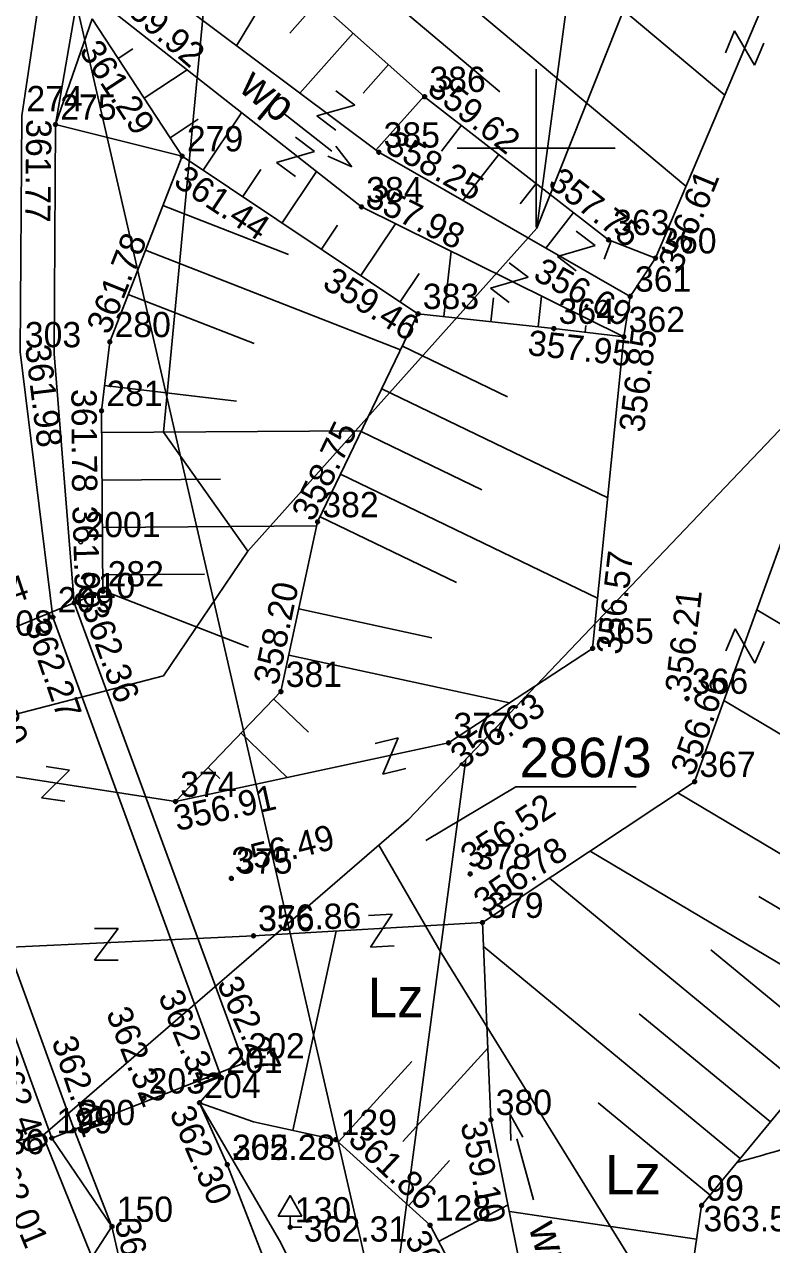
# Model space of a CAD drawing. Extents: x 4635329 to 4651863, y 5356628 to 5367582.
# Drawn here: x 4651733.8 to 4651757.46, y 5357115.3 to 5357153.92 of the extents above; entities that cross this region are included whole.
import ezdxf

# ---------------------------------------------------------------- set-up
doc = ezdxf.new("R2010")
doc.units = 0
for name, color, linetype in [('Level 12', 7, 'Continuous'), ('Level 2', 7, 'Continuous'), ('Level 20', 7, 'Continuous'), ('Level 24', 7, 'Continuous'), ('Level 29', 7, 'Continuous'), ('Level 4', 7, 'Continuous'), ('Level 44', 7, 'Continuous'), ('Level 45', 7, 'Continuous'), ('Level 46', 7, 'Continuous'), ('Level 48', 7, 'Continuous'), ('Level 5', 7, 'Continuous'), ('Level 50', 7, 'Continuous'), ('Level 51', 7, 'Continuous'), ('Level 53', 7, 'Continuous'), ('Level 60', 7, 'Continuous'), ('Level 63', 7, 'Continuous')]:
    doc.layers.add(name, color=color, linetype=linetype)

msp = doc.modelspace()

# ---------------------------------------------------------------- linework, layer by layer
at = {"layer": 'Level 2'}
msp.add_line((4651752.271, 5357081.395), (4651734.633, 5357158.117), dxfattribs=at)
at = {"layer": 'Level 20'}
for p, q in [((4651734.7, 5357135.16), (4651740.04, 5357120.58)), ((4651739.34, 5357119.79), (4651740.22, 5357117.83)), ((4651740.22, 5357117.83), (4651742.64, 5357111.63))]:
    msp.add_line(p, q, dxfattribs=at)
for points in [[(4651756.54, 5357214.25), (4651747.08, 5357190.33), (4651742.11, 5357177.45), (4651737.72, 5357166.81), (4651734.98, 5357158.12), (4651734.207, 5357154.352), (4651733.71, 5357151.02), (4651733.66, 5357143.55), (4651734.7, 5357135.16)], [(4651730.09, 5357133.42), (4651735.37, 5357118.93)], [(4651729.32, 5357025.03), (4651737.42, 5357039.16), (4651742.88, 5357049.73), (4651744.63, 5357054), (4651745.586, 5357056.87), (4651746.84, 5357061.68), (4651747.431, 5357065.159), (4651747.81, 5357068.95), (4651747.54, 5357079.35), (4651746.07, 5357086.39), (4651738.98, 5357107.74), (4651737.87, 5357110.18), (4651736.57, 5357115.87), (4651735.37, 5357118.93)], [(4651736.57, 5357115.87), (4651734.62, 5357112.86), (4651733.779, 5357107.317), (4651731.11, 5357098.85), (4651730.6, 5357091.37), (4651722.32, 5357083.58)]]:
    msp.add_lwpolyline(points, dxfattribs=at)
at = {"layer": 'Level 24'}
for p, q in [((4651742.21, 5357115.85), (4651742.21, 5357116.2)), ((4651742.585, 5357115.85), (4651742.21, 5357115.85))]:
    msp.add_line(p, q, dxfattribs=at)
msp.add_lwpolyline([(4651742.585, 5357116.2), (4651741.835, 5357116.2), (4651742.21, 5357116.85)], close=True, dxfattribs=at)
at = {"layer": 'Level 29'}
msp.add_lwpolyline([(4651734.66, 5357118.67), (4651740.74, 5357121.04), (4651735.37, 5357135.61), (4651729.39, 5357133.15)], close=True, dxfattribs=at)
at = {"layer": 'Level 4'}
for p, q in [((4651763.487, 5357181.344), (4651750.024, 5357147.467)), ((4651751.63, 5357159.48), (4651750.024, 5357147.467)), ((4651738.202, 5357141.009), (4651739.93, 5357159.265)), ((4651750.024, 5357147.467), (4651740.87, 5357137.248)), ((4651745.963, 5357128.756), (4651762.032, 5357145.618)), ((4651740.87, 5357137.248), (4651738.202, 5357141.009)), ((4651738.202, 5357133.305), (4651740.87, 5357137.248)), ((4651729.077, 5357130.935), (4651738.202, 5357133.305)), ((4651747.779, 5357130.661), (4651745.31, 5357112.19)), ((4651749.355, 5357129.788), (4651746.507, 5357128.092)), ((4651753.172, 5357129.788), (4651749.355, 5357129.788)), ((4651734.382, 5357118.748), (4651745.963, 5357128.756)), ((4651746.966, 5357124.583), (4651745.017, 5357127.939)), ((4651746.966, 5357124.583), (4651754.512, 5357112.38)), ((4651726.932, 5357117.207), (4651734.382, 5357118.748)), ((4651738.719, 5357108.044), (4651734.382, 5357118.748))]:
    msp.add_line(p, q, dxfattribs=at)
at = {"layer": 'Level 44'}
for centre in [(4651746.47, 5357151.63), (4651734.78, 5357150.75), (4651738.79, 5357149.75), (4651745.02, 5357149.87), (4651744.47, 5357148.14), (4651752.29, 5357147.1), (4651753.78, 5357146.52), (4651752.98, 5357145.31), (4651746.26, 5357144.76), (4651750.56, 5357144.29), (4651736.5, 5357143.87), (4651752.78, 5357144.03), (4651736.24, 5357141.69), (4651743.08, 5357138.17), (4651736.28, 5357135.98), (4651735.37, 5357135.61), (4651734.7, 5357135.16), (4651751.79, 5357134.17), (4651741.92, 5357132.8), (4651754.78, 5357132.58), (4651747.23, 5357131.18), (4651755.02, 5357129.95), (4651738.58, 5357129.32), (4651740.35, 5357126.89), (4651747.91, 5357127.03), (4651748.3, 5357125.49), (4651741.05, 5357125.07), (4651740.74, 5357121.04), (4651740.04, 5357120.58), (4651737.58, 5357119.93), (4651739.34, 5357119.79), (4651748.57, 5357119.25), (4651735.37, 5357118.93), (4651734.66, 5357118.67), (4651743.66, 5357118.62), (4651740.22, 5357117.83), (4651755.24, 5357116.54), (4651736.57, 5357115.87), (4651742.21, 5357115.85), (4651746.64, 5357115.91)]:
    msp.add_circle(centre, 0.04, dxfattribs=at)
at = {"layer": 'Level 46'}
for points in [[(4651790.492, 5357125.623), (4651787.46, 5357124.319), (4651783.61, 5357123.258), (4651779.365, 5357124.047), (4651775.849, 5357125.502), (4651773.423, 5357125.502), (4651767.19, 5357123.23), (4651762.733, 5357120.713), (4651758.853, 5357118.681), (4651756.364, 5357117.902)], [(4651754.793, 5357102.394), (4651755.147, 5357104.754), (4651755.905, 5357108.242), (4651755.935, 5357111.456), (4651757.114, 5357114.234), (4651759.084, 5357116.205), (4651762.904, 5357118.146), (4651766.694, 5357118.419), (4651770.685, 5357117.772)]]:
    msp.add_spline(points, degree=3, dxfattribs=at)
at = {"layer": 'Level 48'}
for p, q in [((4651746.469, 5357159.664), (4651755.973, 5357151.681)), ((4651744.54, 5357157.367), (4651754.746, 5357148.794)), ((4651743.575, 5357156.219), (4651748.854, 5357151.784)), ((4651741.877, 5357155.511), (4651740.515, 5357153.245)), ((4651743.091, 5357154.641), (4651742.202, 5357153.644)), ((4651734.78, 5357150.75), (4651735.94, 5357154.09)), ((4651735.94, 5357154.09), (4651738.79, 5357149.75)), ((4651744.211, 5357153.643), (4651742.518, 5357151.744)), ((4651736.763, 5357152.836), (4651737.234, 5357153.145)), ((4651737.587, 5357151.582), (4651738.949, 5357152.477)), ((4651745.331, 5357152.645), (4651744.527, 5357151.743)), ((4651746.451, 5357151.647), (4651744.928, 5357149.939)), ((4651738.41, 5357150.329), (4651739.302, 5357150.914)), ((4651739.462, 5357149.301), (4651740.676, 5357151.12)), ((4651747.633, 5357150.725), (4651747, 5357149.911)), ((4651748.817, 5357149.803), (4651747.682, 5357148.345)), ((4651740.709, 5357148.468), (4651741.284, 5357149.329)), ((4651741.956, 5357147.635), (4651743.043, 5357149.261)), ((4651750.001, 5357148.882), (4651749.499, 5357148.237)), ((4651738.18, 5357148.184), (4651742.16, 5357146.634)), ((4651751.184, 5357147.961), (4651750.311, 5357146.839)), ((4651743.204, 5357146.802), (4651743.715, 5357147.567)), ((4651744.451, 5357145.968), (4651745.546, 5357147.608)), ((4651752.382, 5357147.064), (4651752.158, 5357146.487)), ((4651737.629, 5357146.77), (4651745.711, 5357143.622)), ((4651747.08, 5357144.67), (4651747.306, 5357146.738)), ((4651745.698, 5357145.135), (4651746.3, 5357146.036)), ((4651737.085, 5357145.372), (4651741.071, 5357143.82)), ((4651748.571, 5357144.507), (4651748.654, 5357145.268)), ((4651750.062, 5357144.344), (4651750.169, 5357145.322)), ((4651743.08, 5357138.17), (4651746.26, 5357144.76)), ((4651751.552, 5357144.174), (4651751.578, 5357144.393)), ((4651745.767, 5357143.738), (4651749.097, 5357142.131)), ((4651736.336, 5357142.492), (4651740.51, 5357141.994)), ((4651745.115, 5357142.387), (4651752.268, 5357138.935)), ((4651736.245, 5357140.998), (4651744.472, 5357141.055)), ((4651744.463, 5357141.036), (4651748.286, 5357139.192)), ((4651743.811, 5357139.685), (4651751.949, 5357135.758)), ((4651736.255, 5357139.498), (4651740.001, 5357139.524)), ((4651741.92, 5357132.8), (4651743.08, 5357138.17)), ((4651743.159, 5357138.335), (4651747.475, 5357136.252)), ((4651736.266, 5357137.998), (4651743.053, 5357138.045)), ((4651736.276, 5357136.498), (4651739.502, 5357136.52)), ((4651736.28, 5357136.006), (4651740.891, 5357134.21)), ((4651742.485, 5357135.416), (4651746.699, 5357134.506)), ((4651764.981, 5357130.639), (4651756.987, 5357135.393)), ((4651742.168, 5357133.95), (4651749.153, 5357132.441)), ((4651738.58, 5357129.32), (4651741.92, 5357132.8)), ((4651741.696, 5357132.567), (4651742.793, 5357131.514)), ((4651763.448, 5357128.06), (4651755.949, 5357132.52)), ((4651740.657, 5357131.484), (4651742.119, 5357130.081)), ((4651739.619, 5357130.402), (4651739.984, 5357130.051)), ((4651761.78, 5357125.255), (4651754.483, 5357129.594)), ((4651760.247, 5357122.676), (4651751.71, 5357127.753)), ((4651758.373, 5357120.337), (4651750.422, 5357126.898)), ((4651761.013, 5357123.966), (4651757.055, 5357126.32)), ((4651742.3, 5357118.915), (4651743.667, 5357125.222)), ((4651756.464, 5357118.023), (4651748.333, 5357124.732)), ((4651759.328, 5357121.494), (4651755.528, 5357124.63)), ((4651757.419, 5357119.18), (4651753.267, 5357122.606)), ((4651745.78, 5357118.561), (4651748.472, 5357121.521)), ((4651743.74, 5357118.547), (4651746.06, 5357121.098)), ((4651755.509, 5357116.866), (4651751.965, 5357119.791)), ((4651745.959, 5357116.529), (4651747.261, 5357117.961)), ((4651746.91, 5357115.397), (4651749.112, 5357116.557)), ((4651755.083, 5357115.475), (4651749.154, 5357116.349))]:
    msp.add_line(p, q, dxfattribs=at)
for points in [[(4651788.23, 5357177.15), (4651778.95, 5357165), (4651774.56, 5357160.24), (4651772.52, 5357151.19), (4651770.34, 5357137.07), (4651766.1, 5357132.52), (4651760.1, 5357122.43), (4651755.24, 5357116.54), (4651754.43, 5357111.05), (4651754.06, 5357101.72), (4651764.92, 5357096.97)], [(4651736.04, 5357158.01), (4651734.78, 5357150.75)], [(4651753.78, 5357146.52), (4651752.29, 5357147.1), (4651746.47, 5357151.63), (4651742.61, 5357155.07), (4651738.55, 5357157.51)], [(4651734.78, 5357150.75), (4651734.734, 5357143.494), (4651735.37, 5357135.61)], [(4651735.37, 5357135.61), (4651736.28, 5357135.98), (4651736.24, 5357141.69), (4651736.5, 5357143.87), (4651738.79, 5357149.75), (4651734.78, 5357150.75)], [(4651738.79, 5357149.75), (4651746.26, 5357144.76), (4651750.56, 5357144.29), (4651752.78, 5357144.03)], [(4651739.34, 5357119.79), (4651740.04, 5357120.58)], [(4651739.34, 5357119.79), (4651741.05, 5357119.186), (4651743.66, 5357118.62)], [(4651739.34, 5357119.79), (4651741.917, 5357115.357), (4651743.483, 5357112.18), (4651749.82, 5357100.94)], [(4651734.66, 5357118.67), (4651736.57, 5357115.87)], [(4651749.82, 5357100.94), (4651748.78, 5357111.85), (4651746.64, 5357115.91), (4651743.66, 5357118.62)]]:
    msp.add_lwpolyline(points, dxfattribs=at)
at = {"layer": 'Level 50'}
for p, q in [((4651762.59, 5357167.25), (4651753.78, 5357146.52)), ((4651736.97, 5357155.9), (4651745.02, 5357149.87)), ((4651744.47, 5357148.14), (4651736.5, 5357154.4)), ((4651741.955, 5357151.138), (4651743.53, 5357149.905)), ((4651743.653, 5357150.062), (4651744.16, 5357149.412)), ((4651744.16, 5357149.412), (4651743.406, 5357149.748)), ((4651745.02, 5357149.87), (4651752.98, 5357145.31)), ((4651752.78, 5357144.03), (4651744.47, 5357148.14)), ((4651753.78, 5357146.52), (4651752.98, 5357145.31)), ((4651752.98, 5357145.31), (4651752.78, 5357144.03)), ((4651752.78, 5357144.03), (4651751.79, 5357134.17)), ((4651755.02, 5357129.95), (4651760.04, 5357143.84)), ((4651751.79, 5357134.17), (4651747.23, 5357131.18)), ((4651738.58, 5357129.32), (4651724.05, 5357131.57)), ((4651747.23, 5357131.18), (4651738.58, 5357129.32)), ((4651748.3, 5357125.49), (4651755.02, 5357129.95)), ((4651741.05, 5357125.07), (4651748.3, 5357125.49)), ((4651748.3, 5357125.49), (4651748.57, 5357119.25)), ((4651730.04, 5357124.56), (4651741.05, 5357125.07)), ((4651748.57, 5357119.25), (4651750.15, 5357111.4)), ((4651749.198, 5357118.595), (4651749.181, 5357119.419)), ((4651749.181, 5357119.419), (4651749.584, 5357118.699)), ((4651749.916, 5357116.717), (4651749.391, 5357118.647))]:
    msp.add_line(p, q, dxfattribs=at)
at = {"layer": 'Level 53'}
for p, q in [((4651756.286, 5357153.712), (4651755.993, 5357153.021)), ((4651756.914, 5357152.631), (4651756.286, 5357153.712)), ((4651757.207, 5357153.322), (4651756.914, 5357152.631)), ((4651743.659, 5357151.818), (4651744.257, 5357151.365)), ((4651744.257, 5357151.365), (4651743.056, 5357151.021)), ((4651743.056, 5357151.021), (4651743.654, 5357150.568)), ((4651742.383, 5357150.352), (4651742.983, 5357149.901)), ((4651742.983, 5357149.901), (4651741.783, 5357149.552)), ((4651741.783, 5357149.552), (4651742.383, 5357149.101)), ((4651751.273, 5357147.37), (4651751.873, 5357146.919)), ((4651751.873, 5357146.919), (4651750.673, 5357146.57)), ((4651750.673, 5357146.57), (4651751.273, 5357146.119)), ((4651749.152, 5357146.37), (4651749.752, 5357145.919)), ((4651749.752, 5357145.919), (4651748.552, 5357145.57)), ((4651748.552, 5357145.57), (4651749.152, 5357145.119)), ((4651756.302, 5357134.786), (4651756.005, 5357134.097)), ((4651756.923, 5357133.701), (4651756.302, 5357134.786)), ((4651757.22, 5357134.39), (4651756.923, 5357133.701)), ((4651745.637, 5357131.334), (4651744.908, 5357131.155)), ((4651745.147, 5357130.184), (4651745.637, 5357131.334)), ((4651735.226, 5357130.318), (4651734.485, 5357130.431)), ((4651745.875, 5357130.363), (4651745.147, 5357130.184)), ((4651734.334, 5357129.442), (4651735.226, 5357130.318)), ((4651735.076, 5357129.329), (4651734.334, 5357129.442)), ((4651745.446, 5357125.754), (4651744.697, 5357125.71)), ((4651744.756, 5357124.712), (4651745.446, 5357125.754)), ((4651736.768, 5357125.303), (4651736.018, 5357125.303)), ((4651736.018, 5357124.303), (4651736.768, 5357125.303)), ((4651745.504, 5357124.756), (4651744.756, 5357124.712)), ((4651736.768, 5357124.303), (4651736.018, 5357124.303))]:
    msp.add_line(p, q, dxfattribs=at)
at = {"layer": 'Level 60'}
for p, q in [((4651750, 5357147.5), (4651750, 5357152.5)), ((4651747.5, 5357150), (4651752.5, 5357150))]:
    msp.add_line(p, q, dxfattribs=at)
at = {"layer": 'Level 63'}
for centre in [(4651746.47, 5357151.63), (4651734.78, 5357150.75), (4651738.79, 5357149.75), (4651745.02, 5357149.87), (4651744.47, 5357148.14), (4651752.29, 5357147.1), (4651753.78, 5357146.52), (4651752.98, 5357145.31), (4651746.26, 5357144.76), (4651750.56, 5357144.29), (4651736.5, 5357143.87), (4651752.78, 5357144.03), (4651736.24, 5357141.69), (4651743.08, 5357138.17), (4651735.58, 5357137.54), (4651735.58, 5357137.54), (4651735.58, 5357137.54), (4651735.58, 5357137.54), (4651736.28, 5357135.98), (4651735.37, 5357135.61), (4651734.7, 5357135.16), (4651751.79, 5357134.17), (4651741.92, 5357132.8), (4651754.78, 5357132.58), (4651747.23, 5357131.18), (4651755.02, 5357129.95), (4651738.58, 5357129.32), (4651740.35, 5357126.89), (4651747.91, 5357127.03), (4651748.3, 5357125.49), (4651741.05, 5357125.07), (4651740.74, 5357121.04), (4651740.04, 5357120.58), (4651737.58, 5357119.93), (4651739.34, 5357119.79), (4651748.57, 5357119.25), (4651735.37, 5357118.93), (4651734.66, 5357118.67), (4651743.66, 5357118.62), (4651740.22, 5357117.83), (4651755.24, 5357116.54), (4651736.57, 5357115.87), (4651742.21, 5357115.85), (4651746.64, 5357115.91)]:
    msp.add_circle(centre, 0.06, dxfattribs=at)

# ---------------------------------------------------------------- texts
at = {"layer": 'Level 12'}
for p in [(4651744.671, 5357122.494), (4651752.184, 5357116.889)]:
    msp.add_text('Lz', height=1.25, dxfattribs=at).set_placement(p)
at = {"layer": 'Level 45'}
for s, rotation, p in [('359.92', 318.939, (4651736.594, 5357154.652)), ('361.29', 303.2464, (4651735.51, 5357153.08)), ('359.62', 321.8519, (4651746.51, 5357151.785)), ('361.77', 269.3178, (4651733.857, 5357150.923)), ('358.25', 330.7048, (4651745.177, 5357149.907)), ('361.44', 326.5821, (4651738.478, 5357148.847)), ('357.75', 322.1273, (4651750.335, 5357148.821)), ('356.61', 67.6009, (4651754.574, 5357146.063)), ('357.98', 333.8526, (4651744.54, 5357148.215)), ('361.78', 68.2406, (4651736.478, 5357144.065)), ('359.46', 327.8466, (4651743.19, 5357145.612)), ('356.69', 331.5925, (4651749.866, 5357145.87)), ('357.95', 353.6699, (4651749.706, 5357143.456)), ('356.85', 82.8332, (4651753.411, 5357140.978)), ('361.98', 276.9697, (4651733.818, 5357143.741)), ('361.78', 270.414, (4651735.283, 5357142.378)), ('358.75', 64.3032, (4651742.941, 5357138.145)), ('361.99', 271.7322, (4651735.314, 5357138.671)), ('356.57', 83.2861, (4651752.695, 5357133.948)), ('362.34', 18.5727, (4651730.894, 5357134.73)), ('358.20', 78.1938, (4651741.818, 5357132.968)), ('356.21', 83.3487, (4651754.875, 5357132.728)), ('362.36', 289.992, (4651735.599, 5357135.452)), ('362.27', 289.265, (4651733.797, 5357134.952)), ('362.30', 293.5316, (4651731.921, 5357133.983)), ('356.66', 70.5614, (4651754.986, 5357130.084)), ('356.63', 34.0424, (4651747.642, 5357130.318)), ('356.91', 12.533, (4651738.63, 5357128.382)), ('356.52', 33.2512, (4651747.949, 5357127.161)), ('356.49', 14.3811, (4651740.507, 5357127.026)), ('356.78', 34.7211, (4651748.38, 5357125.735)), ('356.86', 1.6831, (4651741.202, 5357125.221)), ('362.27', 294.451, (4651739.877, 5357123.567)), ('362.34', 291.8337, (4651738.023, 5357123.17)), ('362.32', 291.6619, (4651736.371, 5357122.631)), ('362.41', 288.2847, (4651734.65, 5357121.746)), ('362.40', 290.1915, (4651732.728, 5357121.191)), ('362.30', 293.51, (4651738.378, 5357119.479)), ('359.10', 281.7376, (4651747.604, 5357119.123)), ('361.86', 316.8907, (4651744.003, 5357118.572)), ('362.01', 292.5802, (4651732.591, 5357118.141)), ('362.36', 283.4045, (4651736.644, 5357116.025)), ('361.90', 298.0066, (4651745.82, 5357115.477))]:
    msp.add_text(s, height=0.8, rotation=rotation, dxfattribs=at).set_placement(p)
for s, p in [('362.28', (4651740.37, 5357117.98)), ('363.57', (4651755.299, 5357115.72)), ('362.31', (4651742.648, 5357115.394))]:
    msp.add_text(s, height=0.8, dxfattribs=at).set_placement(p)
at = {"layer": 'Level 5'}
msp.add_text('286/3', height=1.25, dxfattribs=at).set_placement((4651749.476, 5357130.092))
at = {"layer": 'Level 51'}
for rotation, p in [(320.5701, (4651740.54, 5357151.848)), (286.7595, (4651749.752, 5357115.861))]:
    msp.add_text('wp', height=1, rotation=rotation, dxfattribs=at).set_placement(p)
at = {"layer": 'Level 63'}
for s, p in [('386', (4651746.62, 5357151.78)), ('274', (4651733.86, 5357151.17)), ('275', (4651734.93, 5357150.9)), ('385', (4651745.17, 5357150.02)), ('279', (4651738.94, 5357149.9)), ('384', (4651744.62, 5357148.29)), ('363', (4651752.44, 5357147.25)), ('360', (4651753.93, 5357146.67)), ('361', (4651753.13, 5357145.46)), ('383', (4651746.41, 5357144.91)), ('364', (4651750.71, 5357144.44)), ('280', (4651736.65, 5357144.02)), ('362', (4651752.93, 5357144.18)), ('303', (4651733.81, 5357143.7)), ('281', (4651736.39, 5357141.84)), ('382', (4651743.23, 5357138.32)), ('2001', (4651735.73, 5357137.69)), ('2001', (4651735.73, 5357137.69)), ('2001', (4651735.73, 5357137.69)), ('2001', (4651735.73, 5357137.69)), ('282', (4651736.43, 5357136.13)), ('210', (4651735.52, 5357135.76)), ('209', (4651734.85, 5357135.31)), ('208', (4651732.91, 5357134.57)), ('365', (4651751.94, 5357134.32)), ('381', (4651742.07, 5357132.95)), ('366', (4651754.93, 5357132.73)), ('377', (4651747.38, 5357131.33)), ('367', (4651755.17, 5357130.1)), ('374', (4651738.73, 5357129.47)), ('375', (4651740.5, 5357127.04)), ('378', (4651748.06, 5357127.18)), ('379', (4651748.45, 5357125.64)), ('376', (4651741.2, 5357125.22)), ('202', (4651740.89, 5357121.19)), ('201', (4651740.19, 5357120.73)), ('203', (4651737.73, 5357120.08)), ('204', (4651739.49, 5357119.94)), ('380', (4651748.72, 5357119.4)), ('199', (4651734.81, 5357118.82)), ('200', (4651735.52, 5357119.08)), ('129', (4651743.81, 5357118.77)), ('136', (4651732.64, 5357118.16)), ('205', (4651740.37, 5357117.98)), ('99', (4651755.39, 5357116.69)), ('150', (4651736.72, 5357116.02)), ('128', (4651746.79, 5357116.06)), ('130', (4651742.36, 5357116))]:
    msp.add_text(s, height=0.8, dxfattribs=at).set_placement(p)

doc.saveas('drawing.dxf')
